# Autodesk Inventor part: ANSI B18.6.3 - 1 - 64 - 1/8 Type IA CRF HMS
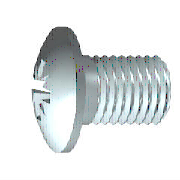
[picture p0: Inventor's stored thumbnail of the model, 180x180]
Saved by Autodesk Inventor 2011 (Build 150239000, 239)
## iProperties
IsCustomPart: 0
Created: 2008-01
Part Number: ANSI B18.6.3 - 1 - 64 - 1/8 Type IA CRF HMS
Material: Steel, Mild
Description: Cross Recessed Fillister Head Machine Screw - Type IA
Document SubType Name: Modeling
Standard: ANSI B18.6.3
Standard Revision: 2003
Standards Organization: ANSI
Language: en-US
Size Designation: 1 - 64 - 1/8
Categories: <MemberInstance><Categories><Category DisplayName="Fasteners" InternalName="e4da775c-781d-43d5-af7c-5136215cf5a6" Mnemonic="FSTN"><Category DisplayName="Bolts"
Density: 1 g/cm^3
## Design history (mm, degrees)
body "Solid1"
workplane "Work Plane3"
sketch "Sketch4"
  geometry: L1 (-9, 0)-(9, 0) reference; L2 (0, -9)-(0, 9) reference; L3 (0, 0)-(6.428, 6.428); L4 (0, 0)-(6.428, -6.428); L5 (0, 0)-(-6.428, 6.428); L6 (0, 0)-(-6.428, -6.428); L7 (0.665, 0.665)-(0, 0.152); L8 (-0.665, 0.665)-(-0.152, 0); L9 (-0.665, -0.665)-(0, -0.152); L10 (0.665, -0.665)-(0.152, 0); L11 (0.665, 0.665)-(0.152, 0); L12 (-0.665, 0.665)-(0, 0.152); L13 (-0.665, -0.665)-(-0.152, 0); L14 (0.665, -0.665)-(0, -0.152); C1 r 1.499 at (0, 0) reference; A1 r 0.152 centre (0, 0) between (0, 0.152) and (-0.152, 0); A2 r 0.94 centre (0, 0) between (0.665, 0.665) and (0.665, -0.665); 1 further point
  constraints: 24 end point, 10 point on line, 7 point on circle, 3 perpendicular, 3 symmetric about line, 2 centre point, 2 coincident, 3 other
  dimensions: "d11" = 0.3048 diameter of A1 (= 0.666667 x SBR); "d14" = 45 deg angle of L3 L1; "d28" = 0.66454 distance from line of L1 L7.start (= 0.353553 x SDM)
extrude "Star Cut" cut sketch "Sketch4" distance "d12" = 1.6764 (= KOH); taper "d13" = -30 deg
sketch "Sketch2"
  geometry: L1 (-3.142, 0)-(8.365, 0) reference; L2 (0, -3.142)-(0, 8.365) reference; L3 (0, 0.94)-(0, 0); L4 (0, 0)-(0.94, 0); L5 (0, 0)-(6.721, 6.721); L6 (0.229, 0.912)-(0.137, 0.45); L7 (0.912, 0.229)-(0.45, 0.137); L8 (0.912, -0.229)-(0.45, -0.137); L9 (0.229, -0.912)-(0.137, -0.45); L10 (-0.229, 0.912)-(-0.137, 0.45); L11 (-0.912, 0.229)-(-0.45, 0.137); L12 (-0.229, -0.912)-(-0.137, -0.45); L13 (-0.912, -0.229)-(-0.45, -0.137); C1 r 1.499 at (0, 0) reference; A1 r 0.376 centre (0, 0) between (0.376, 0) and (0, 0.376); A2 r 0.121 centre (0.255, 0.426) between (0.137, 0.45) and (0.341, 0.341); A3 r 0.121 centre (0.426, 0.255) between (0.341, 0.341) and (0.45, 0.137); A4 r 0.94 centre (0, 0) between (0.94, 0) and (0.912, 0.229); A5 r 0.94 centre (0, 0) between (0.229, 0.912) and (0, 0.94); A6 r 0.94 centre (0, 0) between (0.912, 0.229) and (0.229, 0.912); A7 r 0.94 centre (0, 0) between (0, -0.94) and (0.229, -0.912); A8 r 0.94 centre (0, 0) between (0.229, -0.912) and (0.912, -0.229); A9 r 0.94 centre (0, 0) between (0.912, -0.229) and (0.94, 0); A10 r 0.121 centre (0.255, -0.426) between (0.341, -0.341) and (0.137, -0.45); A11 r 0.121 centre (0.426, -0.255) between (0.45, -0.137) and (0.341, -0.341); A12 r 0.121 centre (-0.255, 0.426) between (-0.341, 0.341) and (-0.137, 0.45); A13 r 0.121 centre (-0.426, 0.255) between (-0.45, 0.137) and (-0.341, 0.341); A14 r 0.94 centre (0, 0) between (-0.912, 0.229) and (-0.94, 0); A15 r 0.94 centre (0, 0) between (-0.229, 0.912) and (-0.912, 0.229); A16 r 0.94 centre (0, 0) between (0, 0.94) and (-0.229, 0.912); A17 r 0.94 centre (0, 0) between (-0.94, 0) and (-0.912, -0.229); A18 r 0.94 centre (0, 0) between (-0.912, -0.229) and (-0.229, -0.912); A19 r 0.94 centre (0, 0) between (-0.229, -0.912) and (0, -0.94); A20 r 0.121 centre (-0.426, -0.255) between (-0.341, -0.341) and (-0.45, -0.137); A21 r 0.121 centre (-0.255, -0.426) between (-0.137, -0.45) and (-0.341, -0.341); A22 r 0.47 centre (0, 0) between (0.47, 0) and (0, 0.47)
  constraints: 46 point on circle, 25 symmetric about line, 22 centre point, 22 end point, 6 tangent, 4 coincident, 3 collinear, 3 point on line, 1 midpoint, 1 perpendicular, 22 other
  dimensions: "d4" = 45 deg angle of L5 L4; "d5" = 0.75184 diameter of A1 (= 0.4 x SDM); "d6" = 1.8796 diameter of A6 (= SDM); "d7" = 0.2286 distance from line of L6.start L3 (= 0.5 x SBR); "d20" = 0.9398 diameter of A22 (= 0.5 x SDM)
extrude "Slot" join sketch "Sketch2" taper "d21" = 5 deg; stored distance "d54" = 10
revolve "Cut" stored, may be unused: angle "d56" = 90 deg
revolve "Body" stored, may be unused: angle "d18" = 90 deg
node "IDS_WORKPLANE{1}"
sketch "Sketch1"
  geometry: L1 (3.175, 0)-(3.175, 0.927); L2 (3.175, 0.927)-(0, 0.927); L3 (3.962, 5.08)-(3.962, 5.08); L4 (-1.676, 0)-(-1.676, 1.499); L5 (-1.484, 0.844)-(-0.732, 0.469); L6 (-0.732, 0.469)-(-0.483, 0); L7 (-0.483, 0)-(3.175, 0); L8 (-3.005, 0)-(5.124, 0) reference; L9 (0, -1.016)-(0, 6.096) reference; L10 (-1.484, 0.844)-(-1.676, 0.94); L11 (-0.973, 1.499)-(-1.676, 1.499); L12 (-0.973, 1.499)-(0, 1.499); L13 (0, 1.499)-(0, 0.927); A1 r 1.948 centre (0.272, 0) between (-0.973, 1.499) and (-1.676, 0)
  constraints: 22 end point, 4 collinear, 4 point on circle, 3 point on line, 2 parallel, 1 centre point, 1 horizontal, 1 perpendicular, 1 tangent
  dimensions: "d1" = 1.8542 diameter of L2 L7 (= GD); "d2" = 1.1938 distance from line of L6.end L4 (= STI); "d16" = 1.8796 diameter of L10.end L7 (= SDM); "d17" = 62 deg angle of L6 L7; "d19" = 26.5 deg angle of L5 L7; "d23" = 2.9972 diameter of L12.end L7 (= KOD); "d24" = 0 deg angle of L12 L7 (computed from KEWI); "d25" = 1.6764 distance between parallel lines of L4 L13 (= KOH); "d26" = 1.94818 radius of A1 (= KR); "d77" = 3.175 distance between parallel lines of L13 L1 (= NLG)
fillet "Fillet1" dims "d22" = 0.09144 (= 0.2 x SBR)
feature "Thread" dims "d8" = 2.18281 (= GEL), "d9" = 0
chamfer "Chamfer" distance "d78" = 0.19844 (= 0.5 x RR); stored, may be unused: second distance "d79" = 2, angle "d80" = 45 deg
other parameters: "GD" = 1.8542 (= NND) [user parameter; used in 1 equation term], "NLG" = 3.175 [user parameter; used in 1 equation term], "GEL" = 2.18281 [user parameter; used in 1 equation term], "KOD" = 2.9972 [user parameter; used in 3 equation terms], "KOH" = 1.6764 [user parameter; used in 3 equation terms], "SDM" = 1.8796 [user parameter; used in 5 equation terms], "STI" = 1.1938 [user parameter; used in 1 equation term], "SBR" = 0.4572 [user parameter; used in 3 equation terms], "KEWI" = 0 [user parameter; used in 1 equation term], "d3" = -1.6764 (= -KOH), "d10" = 0, "KR" = 1.94818 (= 0.65 x KOD) [user parameter; used in 1 equation term], "d75" = 0, "d76" = 0, "RR" = 0.39687 (computed from TPU) [user parameter; used in 1 equation term], "KKR" = 0.38964 (= 0.13 x KOD) [user parameter], "SPD" = 1.45733 (= GD1) [user parameter], "PTC" = 0.39687 (computed from TPU) [user parameter], "THREADDIA" = 1.8542 [user parameter], "TOA" = 30 deg [user parameter], "BDM" = 1.8542 (= NND) [user parameter], "NND" = 1.8542 [user parameter; used in 2 equation terms], "GUL" = 0 [user parameter], "GAL" = 0.39687 [user parameter], "GD1" = 1.45733 [user parameter; used in 1 equation term]
